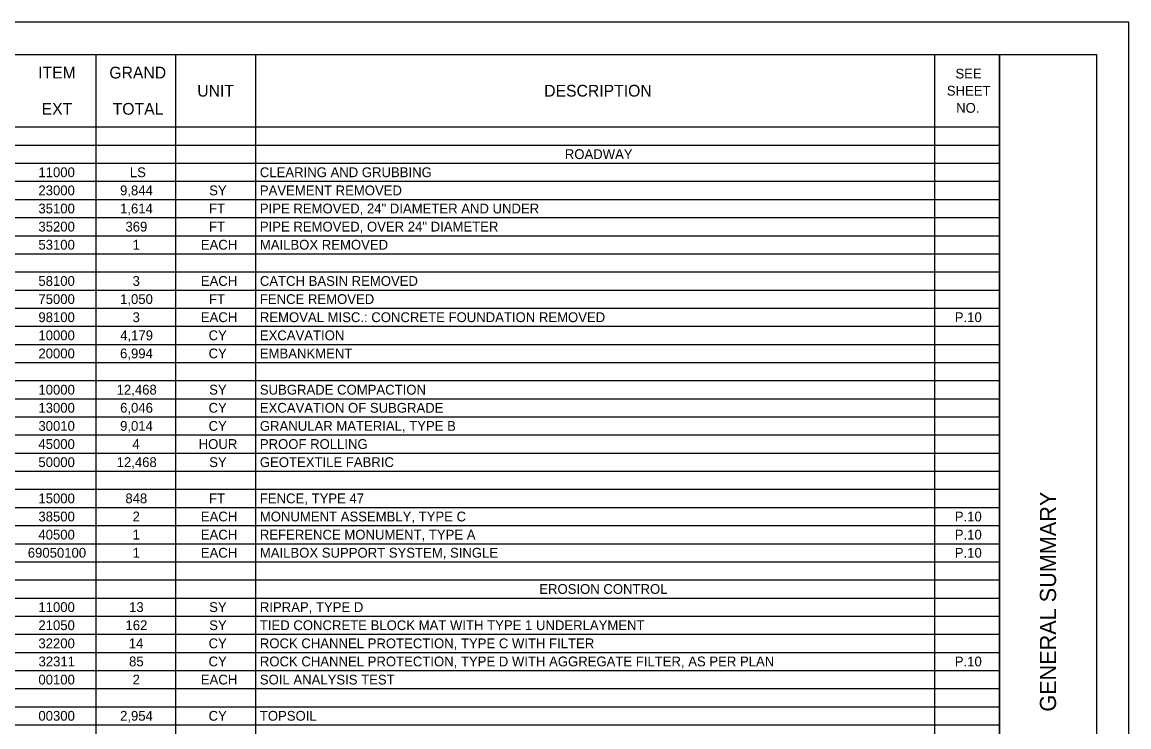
# Model space of a CAD drawing. Extents: x 0 to 34, y 0 to 22.
# Drawn here: x 16.9 to 34, y 11.11 to 22 of the extents above; entities that cross this region are included whole.
import ezdxf

# ---------------------------------------------------------------- set-up
doc = ezdxf.new("R2010")
doc.units = 0
for name, color, linetype in [('SH_Border', 7, 'Continuous'), ('SH_Cut_Line', 7, 'Continuous'), ('SH_Data', 7, 'Continuous'), ('SH_Text', 7, 'Continuous')]:
    doc.layers.add(name, color=color, linetype=linetype)

msp = doc.modelspace()

# ---------------------------------------------------------------- linework, layer by layer
at = {"layer": 'SH_Border'}
msp.add_line((32, 0.5), (32, 21.5), dxfattribs=at)
msp.add_lwpolyline([(1.5, 21.5), (33.5, 21.5), (33.5, 0.5), (1.5, 0.5)], close=True, dxfattribs=at)
at = {"layer": 'SH_Cut_Line'}
msp.add_lwpolyline([(0, 0), (34, 0), (34, 22), (0, 22)], close=True, dxfattribs=at)
at = {"layer": 'SH_Text'}
for p, q in [((1.5, 21.5), (32, 21.5)), ((18.035, 21.5), (18.035, 0.5)), ((19.27, 21.5), (19.27, 0.5)), ((20.505, 21.5), (20.505, 0.5)), ((30.995, 21.5), (30.995, 0.5)), ((32, 21.5), (32, 0.5)), ((1.5, 20.38), (32, 20.38)), ((1.5, 20.1), (32, 20.1)), ((1.5, 19.82), (32, 19.82)), ((1.5, 19.54), (32, 19.54)), ((1.5, 19.26), (32, 19.26)), ((1.5, 18.98), (32, 18.98)), ((1.5, 18.7), (32, 18.7)), ((1.5, 18.42), (32, 18.42)), ((1.5, 18.14), (32, 18.14)), ((1.5, 17.86), (32, 17.86)), ((1.5, 17.58), (32, 17.58)), ((1.5, 17.3), (32, 17.3)), ((1.5, 17.02), (32, 17.02)), ((1.5, 16.74), (32, 16.74)), ((1.5, 16.46), (32, 16.46)), ((1.5, 16.18), (32, 16.18)), ((1.5, 15.9), (32, 15.9)), ((1.5, 15.62), (32, 15.62)), ((1.5, 15.34), (32, 15.34)), ((1.5, 15.06), (32, 15.06)), ((1.5, 14.78), (32, 14.78)), ((1.5, 14.5), (32, 14.5)), ((1.5, 14.22), (32, 14.22)), ((1.5, 13.94), (32, 13.94)), ((1.5, 13.66), (32, 13.66)), ((1.5, 13.38), (32, 13.38)), ((1.5, 13.1), (32, 13.1)), ((1.5, 12.82), (32, 12.82)), ((1.5, 12.54), (32, 12.54)), ((1.5, 12.26), (32, 12.26)), ((1.5, 11.98), (32, 11.98)), ((1.5, 11.7), (32, 11.7)), ((1.5, 11.42), (32, 11.42)), ((1.5, 11.14), (32, 11.14))]:
    msp.add_line(p, q, dxfattribs=at)

# ---------------------------------------------------------------- texts
at = {"layer": 'SH_Data'}
msp.add_text('GENERAL SUMMARY', height=0.25, rotation=90, dxfattribs=at).set_placement((32.875, 11.344))
at = {"layer": 'SH_Text'}
for s, height, p in [('ITEM', 0.1818, (17.145, 21.129)), ('GRAND', 0.1818, (18.245, 21.129)), ('SEE ', 0.1515, (31.32, 21.129)), ('UNIT', 0.1818, (19.604, 20.849)), ('DESCRIPTION', 0.18184, (24.965, 20.849)), ('SHEET ', 0.1515, (31.187, 20.864)), ('EXT', 0.1818, (17.199, 20.569)), ('TOTAL', 0.1818, (18.297, 20.569)), ('NO.', 0.1515, (31.331, 20.599)), ('ROADWAY', 0.1515, (25.284, 19.884)), ('11000', 0.1515, (17.149, 19.604)), ('LS', 0.1515, (18.562, 19.604)), ('CLEARING AND GRUBBING', 0.15153, (20.571, 19.604)), ('23000', 0.1515, (17.149, 19.324)), ('9,844', 0.1515, (18.411, 19.324)), ('SY', 0.1515, (19.788, 19.324)), ('PAVEMENT REMOVED', 0.15153, (20.571, 19.324)), ('35100', 0.1515, (17.149, 19.044)), ('1,614', 0.1515, (18.411, 19.044)), ('FT', 0.1515, (19.786, 19.044)), ('PIPE REMOVED, 24" DIAMETER AND UNDER', 0.15153, (20.571, 19.044)), ('35200', 0.1515, (17.149, 18.764)), ('369', 0.1515, (18.494, 18.764)), ('FT', 0.1515, (19.786, 18.764)), ('PIPE REMOVED, OVER 24" DIAMETER', 0.15153, (20.571, 18.764)), ('53100', 0.1515, (17.149, 18.484)), ('1', 0.152, (18.604, 18.484)), ('EACH', 0.1515, (19.659, 18.484)), ('MAILBOX REMOVED', 0.15153, (20.571, 18.484)), ('58100', 0.1515, (17.149, 17.924)), ('3', 0.152, (18.604, 17.924)), ('EACH', 0.1515, (19.659, 17.924)), ('CATCH BASIN REMOVED', 0.15153, (20.571, 17.924)), ('75000', 0.1515, (17.149, 17.644)), ('1,050', 0.1515, (18.411, 17.644)), ('FT', 0.1515, (19.786, 17.644)), ('FENCE REMOVED', 0.15153, (20.571, 17.644)), ('98100', 0.1515, (17.149, 17.364)), ('3', 0.152, (18.604, 17.364)), ('EACH', 0.1515, (19.659, 17.364)), ('REMOVAL MISC.: CONCRETE FOUNDATION REMOVED', 0.15153, (20.571, 17.364)), ('P.10', 0.1515, (31.31, 17.364)), ('10000', 0.1515, (17.149, 17.084)), ('4,179', 0.1515, (18.413, 17.084)), ('CY', 0.1515, (19.779, 17.084)), ('EXCAVATION', 0.1515, (20.571, 17.084)), ('20000', 0.1515, (17.149, 16.804)), ('6,994', 0.1515, (18.411, 16.804)), ('CY', 0.1515, (19.779, 16.804)), ('EMBANKMENT', 0.1515, (20.571, 16.804)), ('10000', 0.1515, (17.149, 16.244)), ('12,468', 0.1515, (18.358, 16.244)), ('SY', 0.1515, (19.788, 16.244)), ('SUBGRADE COMPACTION', 0.15153, (20.571, 16.244)), ('13000', 0.1515, (17.149, 15.964)), ('6,046', 0.1515, (18.412, 15.964)), ('CY', 0.1515, (19.779, 15.964)), ('EXCAVATION OF SUBGRADE', 0.15153, (20.571, 15.964)), ('30010', 0.1515, (17.149, 15.684)), ('9,014', 0.1515, (18.411, 15.684)), ('CY', 0.1515, (19.779, 15.684)), ('GRANULAR MATERIAL, TYPE B', 0.15153, (20.571, 15.684)), ('45000', 0.1515, (17.149, 15.404)), ('4', 0.152, (18.601, 15.404)), ('HOUR', 0.1515, (19.626, 15.404)), ('PROOF ROLLING', 0.15153, (20.571, 15.404)), ('50000', 0.1515, (17.149, 15.124)), ('12,468', 0.1515, (18.358, 15.124)), ('SY', 0.1515, (19.788, 15.124)), ('GEOTEXTILE FABRIC', 0.15153, (20.571, 15.124)), ('15000', 0.1515, (17.149, 14.564)), ('848', 0.1515, (18.493, 14.564)), ('FT', 0.1515, (19.786, 14.564)), ('FENCE, TYPE 47', 0.15153, (20.571, 14.564)), ('38500', 0.1515, (17.149, 14.284)), ('2', 0.152, (18.604, 14.284)), ('EACH', 0.1515, (19.659, 14.284)), ('MONUMENT ASSEMBLY, TYPE C', 0.15153, (20.571, 14.284)), ('P.10', 0.1515, (31.31, 14.284)), ('40500', 0.1515, (17.149, 14.004)), ('1', 0.152, (18.604, 14.004)), ('EACH', 0.1515, (19.659, 14.004)), ('REFERENCE MONUMENT, TYPE A', 0.15153, (20.571, 14.004)), ('P.10', 0.1515, (31.31, 14.004)), ('69050100', 0.1515, (16.985, 13.724)), ('1', 0.152, (18.604, 13.724)), ('EACH', 0.1515, (19.659, 13.724)), ('MAILBOX SUPPORT SYSTEM, SINGLE', 0.15153, (20.571, 13.724)), ('P.10', 0.1515, (31.31, 13.724)), ('EROSION CONTROL', 0.15153, (24.889, 13.164)), ('11000', 0.1515, (17.149, 12.884)), ('13', 0.1515, (18.55, 12.884)), ('SY', 0.1515, (19.788, 12.884)), ('RIPRAP, TYPE D', 0.15153, (20.571, 12.884)), ('21050', 0.1515, (17.149, 12.604)), ('162', 0.1515, (18.495, 12.604)), ('SY', 0.1515, (19.788, 12.604)), ('TIED CONCRETE BLOCK MAT WITH TYPE 1 UNDERLAYMENT', 0.15153, (20.571, 12.604)), ('32200', 0.1515, (17.149, 12.324)), ('14', 0.1515, (18.546, 12.324)), ('CY', 0.1515, (19.779, 12.324)), ('ROCK CHANNEL PROTECTION, TYPE C WITH FILTER', 0.15153, (20.571, 12.324)), ('32311', 0.1515, (17.151, 12.044)), ('85', 0.1515, (18.55, 12.044)), ('CY', 0.1515, (19.779, 12.044)), ('ROCK CHANNEL PROTECTION, TYPE D WITH AGGREGATE FILTER, AS PER PLAN', 0.15153, (20.571, 12.044)), ('P.10', 0.1515, (31.31, 12.044)), ('00100', 0.1515, (17.149, 11.764)), ('2', 0.152, (18.604, 11.764)), ('EACH', 0.1515, (19.659, 11.764)), ('SOIL ANALYSIS TEST', 0.15153, (20.571, 11.764)), ('00300', 0.1515, (17.149, 11.204)), ('2,954', 0.1515, (18.411, 11.204)), ('CY', 0.1515, (19.779, 11.204)), ('TOPSOIL', 0.1515, (20.571, 11.204))]:
    msp.add_text(s, height=height, dxfattribs=at).set_placement(p)

doc.saveas('drawing.dxf')
